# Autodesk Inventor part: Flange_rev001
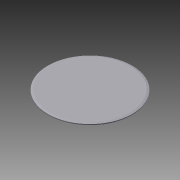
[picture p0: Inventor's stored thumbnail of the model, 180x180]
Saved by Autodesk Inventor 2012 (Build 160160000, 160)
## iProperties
Created: 2011-12
Part Number: Flange_rev001
Document SubType Name: Modeling
Designer: Alex
Density: 2.71 g/cm^3
Material: Aluminum-6061
Mass: 34.2083 g
Surface Area: 165.938 cm^2
Volume: 12.623 cm^3
Author: Alex
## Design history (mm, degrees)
sketch "Sketch1"
  geometry: L1 (0, 0)-(43.993, 0); L2 (43.993, 0)-(46.088, -0.601); L3 (0, -1.578)-(0, 0); L4 (46.088, -0.601)-(46.088, -1.578); L5 (0, -1.893)-(0, 0.316) reference; L6 (46.088, -1.578)-(0, -1.578); 1 further point
  constraints: 10 end point, 3 perpendicular, 2 point on line, 1 horizontal
  dimensions: "d1" = 43.9928 distance of L1.end point (0, 0); "d2" = 164 deg angle of L2 L1; "d11" = 0.60087 vertical distance of L2.end L1.end (derived); "d12" = 1.57752 distance between parallel lines of L6 L1; "d13" = 2.0955 horizontal distance of L2.end L1.end; "d14" = 0.97664 distance of L4.end L2.end (derived); "d15" = 46.0883 distance from line of L4.end L3 (derived)
revolve "Revolution1" sketch "Sketch1" stored, may be unused: angle "d8" = 90 deg
body "Solid1"
